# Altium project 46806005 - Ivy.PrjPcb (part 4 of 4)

## Sheet 510_USB_Type_A_Conn.SchDoc: Ivy - Verdin Industrial Board Rev 1.1
size Letter; Organization: Toradex Solutions Inc.; Address1: 6415 Northwest Drive; Address2: Mississauga, ON, L4V 1X1; Address3: Canada
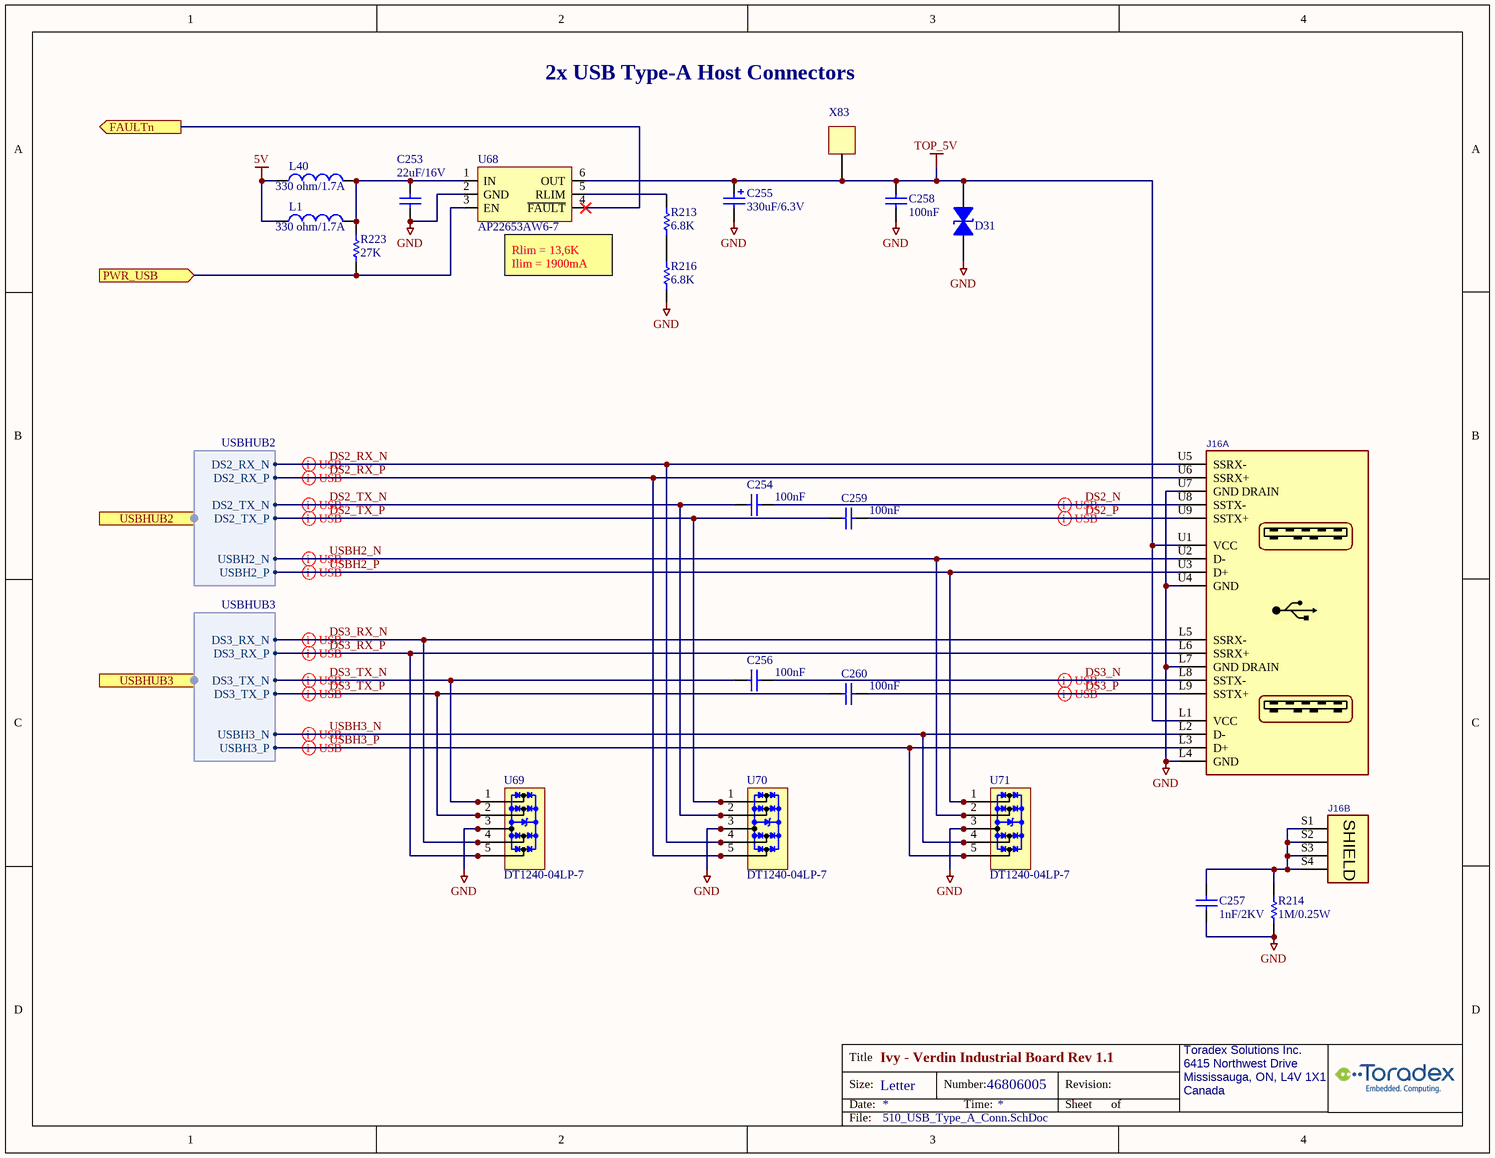
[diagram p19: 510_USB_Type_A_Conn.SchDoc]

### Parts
C253  value 22uF/16V  [C/0805]
C254  100nF  [C0402_CAPC1005L]
C255  330uF/6.3V  [CAN-SMD-D630]
C256  100nF  [C0402_CAPC1005L]
C257  value 1nF/2KV  [C/1206]  (hidden comment: 0567-Cap-1206-1nF/2KV)
C258  100nF  [C0402_CAPC1005L]
C259  100nF  [C0402_CAPC1005L]
C260  100nF  [C0402_CAPC1005L]
D31  D5V0L1B2S9-7  [SOD923_DIO]  (value not drawn)
J16  GSB4112312HR  [T_AMPHENOL_ GSB311231HR]  (value not drawn)  (parts A,B of 2)
L1  value 330 ohm/1.7A  [INDC1608x095]  (hidden comment: 0405-Fer-0603-330ohm/1.7A)
L40  value 330 ohm/1.7A  [INDC1608x095]  (hidden comment: 0405-Fer-0603-330ohm/1.7A)
R213  value 6.8K  [R/0603]  (hidden comment: 0687-Res-0603-6.8K)
R214  value 1M/0.25W  [R/1206]  (hidden comment: 1860-Res-1206-1M-5%-0.25W)
R216  value 6.8K  [R/0603]  (hidden comment: 0687-Res-0603-6.8K)
R223  value 27K  [R0402_RESC1005L]  (hidden comment: 1538-Res-0402-27k)
U68  AP22653AW6-7  [sot23-6]
U69  DT1240-04LP-7  [10-UFDFN]
U70  DT1240-04LP-7  [10-UFDFN]
U71  DT1240-04LP-7  [10-UFDFN]
X83  000-TestPoint  [TestPoint_1]  (value not drawn)

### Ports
FAULTn (out), PWR_USB (in), USBHUB2 (harness USBHUB2), USBHUB3 (harness USBHUB3)

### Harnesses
USBHUB2: USBH2_N, USBH2_P, DS2_TX_N, DS2_TX_P, DS2_RX_N, DS2_RX_P
USBHUB3: USBH3_N, USBH3_P, DS3_TX_N, DS3_TX_P, DS3_RX_N, DS3_RX_P

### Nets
5V: L1.1 L40.1
GND: C253.1 C255.2 C257.1 C258.1 D31.1 J16.L4(GND) J16.L7(GND_DRAIN) J16.U4(GND) J16.U7(GND_DRAIN) R214.2 R216.1 U68.2(GND) U69.3(GND) U69.8(GND) U70.3(GND) U70.8(GND) U71.3(GND) U71.8(GND)
TOP_5V: C255.1 C258.2 D31.2 J16.L1(VCC) J16.U1(VCC) U68.6(OUT) X83.1
DS2_N: C254.1 J16.U8(SSTX-)
DS2_P: C259.1 J16.U9(SSTX+)
DS2_RX_N: J16.U5(SSRX-) U70.4(IO3) U70.7(NC) ; port USBHUB2.DS2_RX_N
DS2_RX_P: J16.U6(SSRX+) U70.5(IO4) U70.6(NC) ; port USBHUB2.DS2_RX_P
DS2_TX_N: C254.2 U70.2(IO2) U70.9(NC) ; port USBHUB2.DS2_TX_N
DS2_TX_P: C259.2 U70.1(IO1) U70.10(NC) ; port USBHUB2.DS2_TX_P
DS3_N: C256.1 J16.L8(SSTX-)
DS3_P: C260.1 J16.L9(SSTX+)
DS3_RX_N: J16.L5(SSRX-) U69.4(IO3) U69.7(NC) ; port USBHUB3.DS3_RX_N
DS3_RX_P: J16.L6(SSRX+) U69.5(IO4) U69.6(NC) ; port USBHUB3.DS3_RX_P
DS3_TX_N: C256.2 U69.1(IO1) U69.10(NC) ; port USBHUB3.DS3_TX_N
DS3_TX_P: C260.2 U69.2(IO2) U69.9(NC) ; port USBHUB3.DS3_TX_P
FAULTn: U68.4(~{FAULT}) ; port FAULTn
PWR_USB: R223.1 U68.3(EN) ; port PWR_USB
USBH2_N: J16.U2(D-) U71.2(IO2) U71.9(NC) ; port USBHUB2.USBH2_N
USBH2_P: J16.U3(D+) U71.1(IO1) U71.10(NC) ; port USBHUB2.USBH2_P
USBH3_N: J16.L2(D-) U71.4(IO3) U71.7(NC) ; port USBHUB3.USBH3_N
USBH3_P: J16.L3(D+) U71.5(IO4) U71.6(NC) ; port USBHUB3.USBH3_P
NetC253_2: C253.2 L1.2 L40.2 R223.2 U68.1(IN)
NetC257_2: C257.2 J16.S1(SHIELD) J16.S2(SHIELD) J16.S3(SHIELD) J16.S4(SHIELD) R214.1
NetR213_1: R213.1 R216.2
NetR213_2: R213.2 U68.5(RLIM)

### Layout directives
differential pair; differential pair class USBH2; differential pair class USB: DS2_N, DS2_P, DS2_RX_N, DS2_RX_P, DS2_TX_N, DS2_TX_P, USBH2_N, USBH2_P
differential pair; differential pair class USBH3; differential pair class USB: DS3_N, DS3_P, DS3_RX_N, DS3_RX_P, DS3_TX_N, DS3_TX_P, USBH3_N, USBH3_P

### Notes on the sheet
- 2x USB Type-A Host Connectors
- (near U68) Rlim = 13,6K
  Ilim = 1900mA

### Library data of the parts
C253 = 1314-Cap-0805-22uF/16V: (-55 to 85 DegC) CAP CER 22uF 16V X5R 0805; MfrNo: CL21A226MOQNNNE; Mfr: Samsung; PN: 1314; Alt: CL21A226MOCLRNC,CL21A226KOQNNNG,GRM21BR61C226ME44L,EMK212BBJ226MG-T
C254 C256 C258-C260 = 1566-Cap-0402-100nF/50V: (-55 to 125 DegC AEC) Cap Ceramic 0.1uF 50V X7R 10% 0402; MfrNo: GRT155R71H104KE01D; Mfr: Murata; Alt: CL05B104KB54PNC,GCM155R71H104ME02D,GCM155R71H104KE02D,GCM155R71H104KE02J; PN: 1566
C255 = 2241-Cap-6.6x6.6-330uF/6.3V: (-55 to 105 DegC) CAP ALUM POLY 33UF 6.3V 20% SMD 10mohm 6.6x6.6x6.1mm Ir:3.9A (100kHz); MfrNo: APXF6R3ARA331MF61G; Mfr: United Chemi-Con; PN: 2241
C257 = 0567-Cap-1206-1nF/2KV: CAP CER 1000PF 2KV X7R 1206; Mfr: Johanson Dielectrics Inc.; MfrNo: 202R18W102KV4E; PN: 567; Alt: 478-2956-1-ND; Alt2: 399-4819-1-ND
D31 = 1655-D5V0L1B2S9-7: (-65 to 155 DegC) TVS DIODE Vwm:5V Vcl:14V@6A SOD-923; Mfr: Diodes; PN: 1655
J16 = 1820-Conn-USB3-2x-RA: (-40 to 85 DegC) Conn USB 3.1 Type A R/A TH; Mfr: Amphenol Commercial; PN: 1820
L1 L40 = 0405-Fer-0603-330ohm/1.7A: (-55 to 125 DegC) FERRITE BEAD 330 OHM 0603 1.7A 80mohm, typ 48mohm; Mfr: TDK Corporation; MfrNo: MPZ1608S331ATA00; PN: 405; TR: 445-5221-2-ND; DR: 445-5221-6-ND; DR2: 810-MPZ1608S331ATA00
R213 R216 = 0687-Res-0603-6.8K: RES SMD 6.8K OHM 1% 1/10W 0603; Mfr: Yageo; MfrNo: RC0603FR-076K8L; PN: 687; TR: 311-6.80KHRTR-ND
R214 = 1860-Res-1206-1M-5%-0.25W: (-55 to 155 DegC) RES SMD 1M OHM 5% 0.25W 10ppm 1206; Mfr: TE Connectivity; MfrNo: CRGCQ1206J1M0; PN: 1860; Alt: RMCF1206JT1M00, RMCF1206JG1M00, CR1206-JW-105ELF
R223 = 1538-Res-0402-27k: (-55 to 155 DegC AEC) RES 27K OHM 1% 1/16W 100ppm 0402; Mfr: Stackpole Electronics; MfrNo: RMCF0402FT27K0; PN: 1538; Alt: AC0402FR-0727KL,CRGCQ0402F27K
U68 = 1475-AP22653: (-40 to 85 DegC) IC PWR SWITCH 3-5.5V EN-Active-High ENth:1.5V With-Discharge 65mohm typ ADJ 0.1-2.1A 6SSOP; Mfr: Diodes; PN: 1475; Note: Similar: BD2222G, BD2242G, TPS25221, TPS2553, RT9728A, RT9728B, RT9728C, AP2553, MIC2009YM6, MIC2019YM6, MIC2009A-1YM6,MIC2019A-1YM6
U69-U71 = 1657-DT1240-04LP-7: (-55 to 85 DegC) IC TVS DIODE 4ch Vrm:5.5V Vcl:11V@5.5A 10-UFDFN 0.5mm; Mfr: Diodes; PN: 1657
X83 = 000-TestPoint: Note: this is PCB footprint only, no parts to buy or assemble

## Sheet 815_IO_Connectors.SchDoc: Ivy - Verdin Industrial Board Rev 1.1
size Letter; Organization: Toradex Solutions Inc.; Address1: 6415 Northwest Drive; Address2: Mississauga, ON, L4V 1X1; Address3: Canada
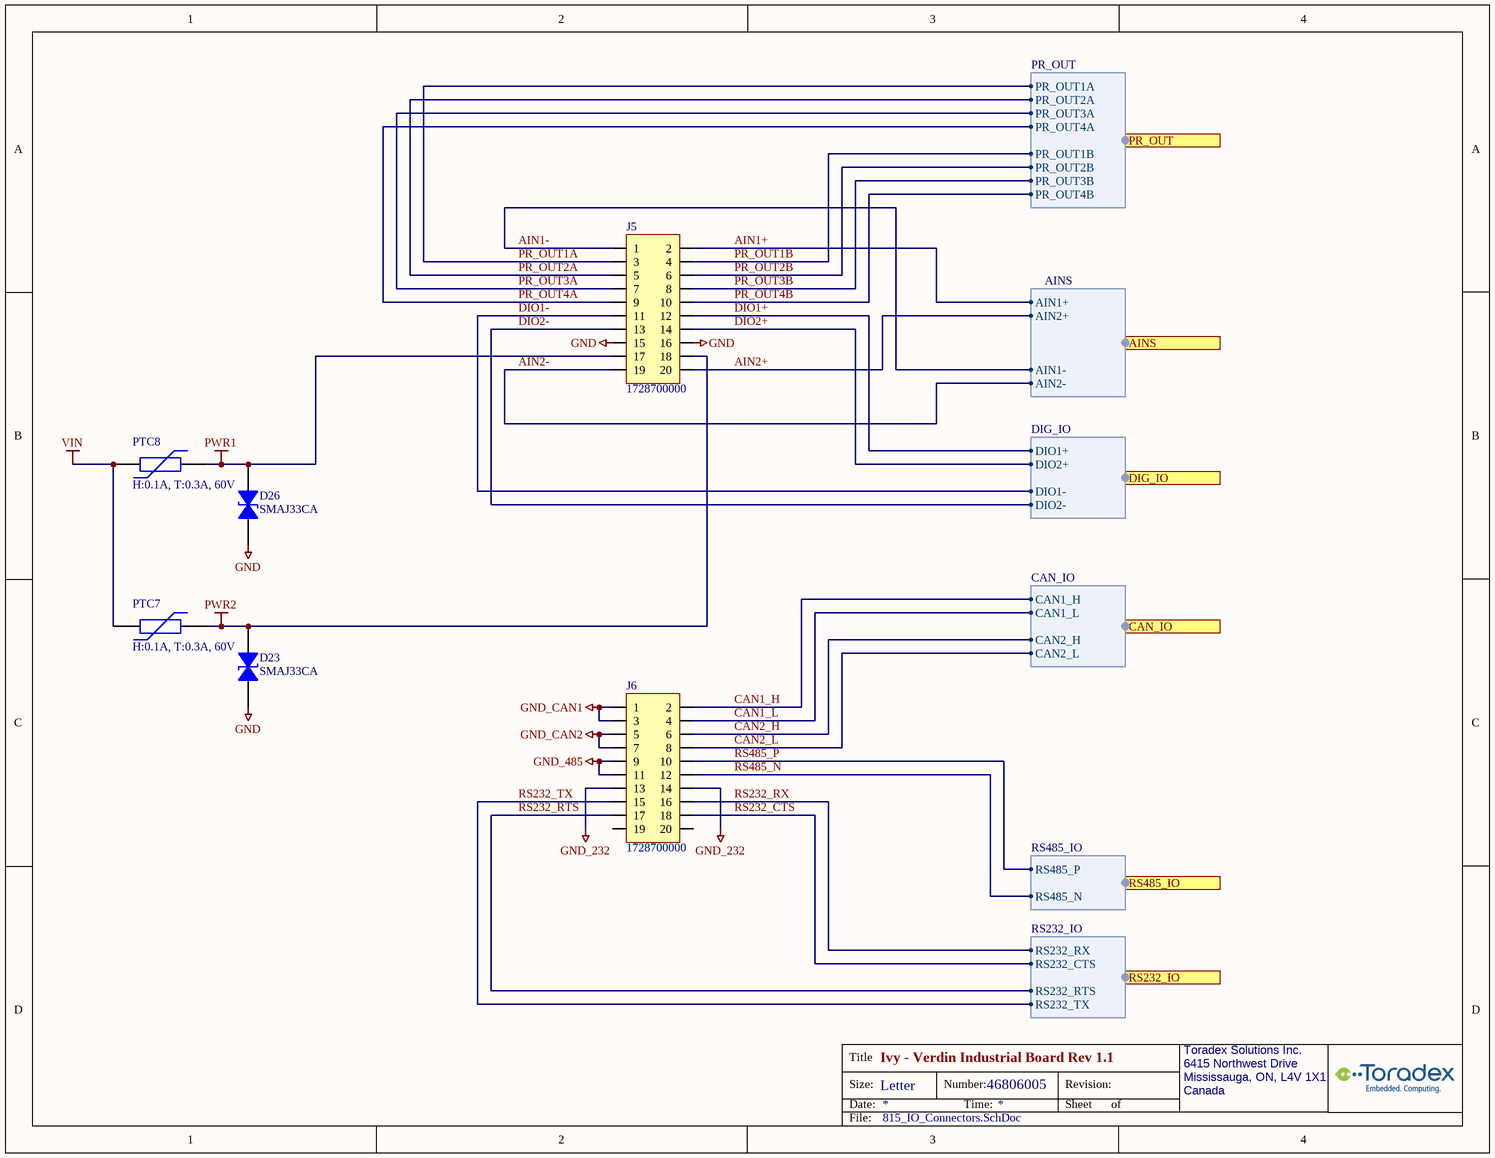
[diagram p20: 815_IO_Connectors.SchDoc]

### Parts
D23  SMAJ33CA  [SMAJ_TRANSIL]
D26  SMAJ33CA  [SMAJ_TRANSIL]
J5  1728700000  [WEIDMULLER_1728700000]
J6  1728700000  [WEIDMULLER_1728700000]
PTC7  H:0.1A, T:0.3A, 60V  [PTC_1812]
PTC8  H:0.1A, T:0.3A, 60V  [PTC_1812]

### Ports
AINS (harness AINS), CAN_IO (harness CAN_IO), DIG_IO (harness DIG_IO), PR_OUT (harness PR_OUT), RS232_IO (harness RS232_IO), RS485_IO (harness RS485_IO)

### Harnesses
PR_OUT: PR_OUT1A, PR_OUT1B, PR_OUT2A, PR_OUT2B, PR_OUT3A, PR_OUT3B, PR_OUT4A, PR_OUT4B
DIG_IO: DIO1+, DIO1-, DIO2+, DIO2-
AINS: AIN1+, AIN1-, AIN2+, AIN2-
CAN_IO: CAN2_H, CAN2_L, CAN1_H, CAN1_L
RS232_IO: RS232_RX, RS232_CTS, RS232_TX, RS232_RTS
RS485_IO: RS485_N, RS485_P

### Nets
GND: D23.2 D26.2 J5.15 J5.16
GND_232: J6.13 J6.14
GND_485: J6.9 J6.11
GND_CAN1: J6.1 J6.3
GND_CAN2: J6.5 J6.7
PWR1: D26.1 J5.17 PTC8.2
PWR2: D23.1 J5.18 PTC7.2
VIN: PTC7.1 PTC8.1
AIN1+: J5.2 ; port AINS.AIN1+
AIN1-: J5.1 ; port AINS.AIN1-
AIN2+: J5.20 ; port AINS.AIN2+
AIN2-: J5.19 ; port AINS.AIN2-
CAN1_H: J6.2 ; port CAN_IO.CAN1_H
CAN1_L: J6.4 ; port CAN_IO.CAN1_L
CAN2_H: J6.6 ; port CAN_IO.CAN2_H
CAN2_L: J6.8 ; port CAN_IO.CAN2_L
DIO1+: J5.12 ; port DIG_IO.DIO1+
DIO1-: J5.11 ; port DIG_IO.DIO1-
DIO2+: J5.14 ; port DIG_IO.DIO2+
DIO2-: J5.13 ; port DIG_IO.DIO2-
PR_OUT1A: J5.3 ; port PR_OUT.PR_OUT1A
PR_OUT1B: J5.4 ; port PR_OUT.PR_OUT1B
PR_OUT2A: J5.5 ; port PR_OUT.PR_OUT2A
PR_OUT2B: J5.6 ; port PR_OUT.PR_OUT2B
PR_OUT3A: J5.7 ; port PR_OUT.PR_OUT3A
PR_OUT3B: J5.8 ; port PR_OUT.PR_OUT3B
PR_OUT4A: J5.9 ; port PR_OUT.PR_OUT4A
PR_OUT4B: J5.10 ; port PR_OUT.PR_OUT4B
RS232_CTS: J6.18 ; port RS232_IO.RS232_CTS
RS232_RTS: J6.17 ; port RS232_IO.RS232_RTS
RS232_RX: J6.16 ; port RS232_IO.RS232_RX
RS232_TX: J6.15 ; port RS232_IO.RS232_TX
RS485_N: J6.12 ; port RS485_IO.RS485_N
RS485_P: J6.10 ; port RS485_IO.RS485_P

Not connected (* = marked no-connect by the designer): J6 19 20

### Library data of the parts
D23 D26 = 0581-SMAJ33CA: (-55 to 150 DegC) TVS DIODE 33VWM Vbrm:36.7V Vcl:53.3V 400W SMA; MfrNo: SMAJ33CA-E3/5A; Mfr: Vishay Semiconductor Diodes Division; PN: 581; Desc: (-55 to 150 DegC) TVS DIODE 33VWM Vbrm:36.7V Vstd:53.3VC SMA; Alt: SMAJ33CA-E3/61GICT-ND; Alt2: SMAJ33CABCT-ND; DR: SMAJ33CA-E3/5AGIDKR-ND; DR2: 625-SMAJ33CA-E3/5A
J5 J6 = 2319-Conn-Hdr-2x10pin-RA-Flanges: (-50 to 100 DegC) TERM BLOCK HDR 20POS 90DEG 3.5MM; Mfr: Weidmuller; PN: 2319
PTC7 PTC8 = 1423-PTC-0.1A-60V-1812: (-40 to 85 DegC) PTC Ih:0.1A, It:0.3A, 60V, 1812, 1.6-15ohm; MfrNo: 0ZCG0010FF2C; Mfr: Bel; PN: 1423; Alt: MPTS1812L010R,MPTS1812L010,1812L010/60DR,PTSA181260V010,MF-MSMF010-2,PFMF.010.2,MINISMDC010F-2,MINIASMDC010F-2

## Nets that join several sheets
1V8: 100_Power (R56.2), 400_USB1_OTG (R58.2 R61.2), 220_Verdin_Full (10 pins), 800_Peripherals (14 pins), 240_Translators (8 pins), 900_LTE (L29.1 R133.1), 300_CAN_Transceivers (L25.1), 620_Ethernet2 (25 pins), 820_MicroSD (R157.2), 840_ADC (9 pins), 850_DIGIN (L32.2)
2V5: 500_USB_Hub (R22.2), 620_Ethernet2 (11 pins)
3V3: 100_Power (9 pins), 600_Ethernet (J10.11 J10.13), 220_Verdin_Full (R270.1 R271.1), 800_Peripherals (J2.3), 240_Translators (7 pins), 900_LTE (L27.1 L28.1), 500_USB_Hub (12 pins), 700_Relays (8 pins), 150_Status_LEDs (Q13.1 R263.2), 620_Ethernet2 (J7.11 J7.13 L26.1), 820_MicroSD (L31.1), 840_ADC (11 pins), 320_RS-232 (5 pins), 330_RS-485 (C219.1 C220.1 U50.1 U51.1), 810_AUX_Connectors (C251.2 J15.25 L33.1)
5V: 100_Power (16 pins), 400_USB1_OTG (L15.1 L16.1 R59.2), 220_Verdin_Full (C3.1), 800_Peripherals (J2.4), 900_LTE (R138.2), 300_CAN_Transceivers (L24.1), 500_USB_Hub (5 pins), 150_Status_LEDs (D5.1 D7.1 D8.1 D9.1), 620_Ethernet2 (R125.2 R126.2), 840_ADC (12 pins), 320_RS-232 (5 pins), 330_RS-485 (6 pins), 810_AUX_Connectors (L34.1), 510_USB_Type_A_Conn (L1.1 L40.1)
GND: 100_Power (56 pins), 600_Ethernet (7 pins), 400_USB1_OTG (17 pins), 220_Verdin_Full (56 pins), 800_Peripherals (26 pins), 240_Translators (6 pins), 900_LTE (35 pins), 300_CAN_Transceivers (20 pins), 500_USB_Hub (62 pins), 700_Relays (8 pins), 150_Status_LEDs (19 pins), 620_Ethernet2 (57 pins), 820_MicroSD (13 pins), 840_ADC (35 pins), 320_RS-232 (12 pins), 330_RS-485 (13 pins), 850_DIGIN (R197.1 R198.1), 810_AUX_Connectors (36 pins), 510_USB_Type_A_Conn (18 pins), 815_IO_Connectors (D23.2 D26.2 J5.15 J5.16)
GND_232: 320_RS-232 (20 pins), 815_IO_Connectors (J6.13 J6.14)
GND_485: 330_RS-485 (19 pins), 815_IO_Connectors (J6.9 J6.11)
GND_CAN1: 300_CAN_Transceivers (18 pins), 815_IO_Connectors (J6.1 J6.3)
GND_CAN2: 300_CAN_Transceivers (18 pins), 815_IO_Connectors (J6.5 J6.7)
SHLD: 000_Main (H1.0 H2.0 H3.0 H4.0), 100_Power (C102.2 R55.1)
VBAT: 220_Verdin_Full (M1.249), 800_Peripherals (X3.1 XS1.2)
VIN: 100_Power (5 pins), 815_IO_Connectors (PTC7.1 PTC8.1)
AIN1+: 840_ADC (D24.1 RA6.2 U37.4), 815_IO_Connectors (J5.2)
AIN1-: 840_ADC (D24.2 PTC5.1), 815_IO_Connectors (J5.1)
AIN2+: 840_ADC (D25.1 RA7.2 U38.4), 815_IO_Connectors (J5.20)
AIN2-: 840_ADC (D25.2 PTC6.1), 815_IO_Connectors (J5.19)
CAN1_H: 300_CAN_Transceivers (J19.2 U22.7 U24.2), 815_IO_Connectors (J6.2)
CAN1_L: 300_CAN_Transceivers (J18.2 U22.6 U24.1), 815_IO_Connectors (J6.4)
CAN1RX_1V8: 220_Verdin_Full (M1.22), 300_CAN_Transceivers (R227.2 R235.1 U20.3)
CAN1TX_1V8: 220_Verdin_Full (M1.20), 300_CAN_Transceivers (R225.2 R234.1 U20.2)
CAN2_H: 300_CAN_Transceivers (J21.2 U23.7 U25.1), 815_IO_Connectors (J6.6)
CAN2_L: 300_CAN_Transceivers (J20.2 U23.6 U25.2), 815_IO_Connectors (J6.8)
CAN2RX_1V8: 220_Verdin_Full (M1.26), 300_CAN_Transceivers (R228.2 R239.1 U21.3)
CAN2TX_1V8: 220_Verdin_Full (M1.24), 300_CAN_Transceivers (R226.2 R238.1 U21.2)
CTRL_RECOVERY_MICO#: 220_Verdin_Full (M1.246), 800_Peripherals (R218.1)
CTRL_RESET_MICO#: 220_Verdin_Full (M1.260), 800_Peripherals (R219.1)
CTRL_RESET_MOCI#: 220_Verdin_Full (M1.258), 800_Peripherals (R8.1), 620_Ethernet2 (R121.1 U26.43)
CTRL_WAKE1_MICO#: 220_Verdin_Full (M1.252), 900_LTE (R132.1)
DIGI_1: 220_Verdin_Full (M1.56), 850_DIGIN (R197.2 U62.3)
DIGI_2: 220_Verdin_Full (M1.58), 850_DIGIN (R198.2 U63.3)
DIO1+: 850_DIGIN (D27.2 D29.1), 815_IO_Connectors (J5.12)
DIO1-: 850_DIGIN (D27.1 U60.3 U62.2), 815_IO_Connectors (J5.11)
DIO2+: 850_DIGIN (D28.2 D30.1), 815_IO_Connectors (J5.14)
DIO2-: 850_DIGIN (D28.1 U61.3 U63.2), 815_IO_Connectors (J5.13)
DS2_RX_N: 500_USB_Hub (U8.44), 510_USB_Type_A_Conn (J16.U5 U70.4 U70.7)
DS2_RX_P: 500_USB_Hub (U8.45), 510_USB_Type_A_Conn (J16.U6 U70.5 U70.6)
DS2_TX_N: 500_USB_Hub (U8.42), 510_USB_Type_A_Conn (C254.2 U70.2 U70.9)
DS2_TX_P: 500_USB_Hub (U8.41), 510_USB_Type_A_Conn (C259.2 U70.1 U70.10)
DS3_RX_N: 500_USB_Hub (U8.36), 510_USB_Type_A_Conn (J16.L5 U69.4 U69.7)
DS3_RX_P: 500_USB_Hub (U8.35), 510_USB_Type_A_Conn (J16.L6 U69.5 U69.6)
DS3_TX_N: 500_USB_Hub (U8.39), 510_USB_Type_A_Conn (C256.2 U69.1 U69.10)
DS3_TX_P: 500_USB_Hub (U8.38), 510_USB_Type_A_Conn (C260.2 U69.2 U69.9)
DSI_1_CLK_N: 220_Verdin_Full (M1.35), 810_AUX_Connectors (L38.2)
DSI_1_CLK_P: 220_Verdin_Full (M1.37), 810_AUX_Connectors (L38.1)
DSI_1_D0_N: 220_Verdin_Full (M1.47), 810_AUX_Connectors (L37.2)
DSI_1_D0_P: 220_Verdin_Full (M1.49), 810_AUX_Connectors (L37.1)
DSI_1_D1_N: 220_Verdin_Full (M1.41), 810_AUX_Connectors (L35.2)
DSI_1_D1_P: 220_Verdin_Full (M1.43), 810_AUX_Connectors (L35.1)
DSI_1_D2_N: 220_Verdin_Full (M1.29), 810_AUX_Connectors (L36.2)
DSI_1_D2_P: 220_Verdin_Full (M1.31), 810_AUX_Connectors (L36.1)
DSI_1_D3_N: 220_Verdin_Full (M1.23), 810_AUX_Connectors (L39.2)
DSI_1_D3_P: 220_Verdin_Full (M1.25), 810_AUX_Connectors (L39.1)
DSI_BKL_EN: 220_Verdin_Full (M1.21), 810_AUX_Connectors (J15.17 R199.2)
DSI_INT: 220_Verdin_Full (M1.17), 810_AUX_Connectors (J15.19 R200.1)
DSI_SCL: 220_Verdin_Full (M1.55), 810_AUX_Connectors (J15.20 R207.1)
DSI_SDA: 220_Verdin_Full (M1.53), 810_AUX_Connectors (J15.21 R208.1)
ETH1_ACT: 600_Ethernet (R2.2), 220_Verdin_Full (M1.237)
ETH1_D0_N: 600_Ethernet (J10.8 U1.2 U1.9), 220_Verdin_Full (M1.227)
ETH1_D0_P: 600_Ethernet (J10.9 U1.1 U1.10), 220_Verdin_Full (M1.225)
ETH1_D1_N: 600_Ethernet (J10.6 U1.5 U1.6), 220_Verdin_Full (M1.231)
ETH1_D1_P: 600_Ethernet (J10.7 U1.4 U1.7), 220_Verdin_Full (M1.233)
ETH1_D2_N: 600_Ethernet (J10.4 U2.2 U2.9), 220_Verdin_Full (M1.241)
ETH1_D2_P: 600_Ethernet (J10.5 U2.1 U2.10), 220_Verdin_Full (M1.239)
ETH1_D3_N: 600_Ethernet (J10.2 U2.5 U2.6), 220_Verdin_Full (M1.245)
ETH1_D3_P: 600_Ethernet (J10.3 U2.4 U2.7), 220_Verdin_Full (M1.247)
ETH1_LINK: 600_Ethernet (R1.2), 220_Verdin_Full (M1.235)
FAULTn: 500_USB_Hub (R217.1), 510_USB_Type_A_Conn (U68.4)
GPIO1: 220_Verdin_Full (M1.206), 800_Peripherals (R9.1 U3.20 X6.1)
I2C1_SCL: 220_Verdin_Full (M1.14), 800_Peripherals (5 pins), 900_LTE (R229.2)
I2C1_SDA: 220_Verdin_Full (M1.12), 800_Peripherals (5 pins), 900_LTE (R230.2)
I2C4_SCL: 220_Verdin_Full (M1.95), 800_Peripherals (J2.14), 840_ADC (R183.1 U47.3 X64.1)
I2C4_SDA: 220_Verdin_Full (M1.93), 800_Peripherals (J2.16), 840_ADC (R184.1 U47.4 X65.1)
I2S_2_BCLK: 220_Verdin_Full (M1.42), 810_AUX_Connectors (R209.1)
JTAG1_TCK: 220_Verdin_Full (M1.9), 810_AUX_Connectors (J13.4 U66.1)
JTAG1_TDI: 220_Verdin_Full (M1.1), 810_AUX_Connectors (J13.8 U67.1)
JTAG1_TDO: 220_Verdin_Full (M1.5), 810_AUX_Connectors (J13.6 U66.3)
JTAG1_TMS: 220_Verdin_Full (M1.13), 810_AUX_Connectors (J13.2 U66.6)
JTAG1_TRST#: 220_Verdin_Full (M1.3), 810_AUX_Connectors (J13.10 U67.6)
NetC97_1: 100_Power (C97.1 R48.1 R49.2), 220_Verdin_Full (M1.2)
NetC100_1: 100_Power (C100.1 R51.1 R52.2), 220_Verdin_Full (M1.4)
NetC101_1: 100_Power (C101.1 R53.1 R54.2), 220_Verdin_Full (M1.6)
NetC103_1: 100_Power (C103.1 R56.1 R57.2), 220_Verdin_Full (M1.8)
NetJ2_8: 220_Verdin_Full (M1.208), 800_Peripherals (J2.8)
NetJ2_10: 220_Verdin_Full (M1.210), 800_Peripherals (J2.10)
NetJ8_36: 900_LTE (J8.36), 500_USB_Hub (U8.59)
NetJ8_38: 900_LTE (J8.38), 500_USB_Hub (U8.60)
NetJ13_1: 220_Verdin_Full (M1.7), 810_AUX_Connectors (J13.1 U67.3)
NetM1_30: 220_Verdin_Full (M1.30), 150_Status_LEDs (Q1.2 R67.2)
NetM1_32: 220_Verdin_Full (M1.32), 150_Status_LEDs (Q1.5 R70.2)
NetM1_34: 220_Verdin_Full (M1.34), 150_Status_LEDs (Q2.2 R71.2)
NetM1_36: 220_Verdin_Full (M1.36), 150_Status_LEDs (Q2.5 R74.2)
NetM1_44: 220_Verdin_Full (M1.44), 150_Status_LEDs (Q3.5 R78.2)
NetM1_46: 220_Verdin_Full (M1.46), 150_Status_LEDs (Q4.2 R79.2)
NetM1_48: 220_Verdin_Full (M1.48), 150_Status_LEDs (Q4.5 R81.2)
NetM1_54: 220_Verdin_Full (M1.54), 150_Status_LEDs (Q3.2 R75.2)
NetM1_57: 220_Verdin_Full (M1.57 R85.1), 900_LTE (R231.2)
NetM1_59: 220_Verdin_Full (M1.59 R224.1), 900_LTE (R232.2)
NetM1_189: 220_Verdin_Full (M1.189), 620_Ethernet2 (R221.1 U26.44)
NetM1_191: 220_Verdin_Full (M1.191), 620_Ethernet2 (R220.1 U26.17)
NetM1_193: 220_Verdin_Full (M1.193), 620_Ethernet2 (U26.16)
NetM1_197: 220_Verdin_Full (M1.197), 620_Ethernet2 (U26.32)
NetM1_199: 220_Verdin_Full (M1.199), 620_Ethernet2 (R118.2 R120.1 U26.38)
NetM1_201: 220_Verdin_Full (M1.201), 620_Ethernet2 (R114.2 R115.1 U26.33)
NetM1_203: 220_Verdin_Full (M1.203), 620_Ethernet2 (U26.34)
NetM1_205: 220_Verdin_Full (M1.205), 620_Ethernet2 (R116.2 R117.2 U26.35)
NetM1_207: 220_Verdin_Full (M1.207), 620_Ethernet2 (U26.36)
NetM1_211: 220_Verdin_Full (M1.211), 620_Ethernet2 (U26.37)
NetM1_212: 220_Verdin_Full (M1.212), 800_Peripherals (R11.1 U6.1 X11.1)
NetM1_213: 220_Verdin_Full (M1.213), 620_Ethernet2 (U26.29)
NetM1_215: 220_Verdin_Full (M1.215), 620_Ethernet2 (U26.25)
NetM1_216: 220_Verdin_Full (M1.216), 840_ADC (U48.2)
NetM1_217: 220_Verdin_Full (M1.217), 620_Ethernet2 (U26.26)
NetM1_218: 220_Verdin_Full (M1.218), 840_ADC (U48.3)
NetM1_219: 220_Verdin_Full (M1.219), 620_Ethernet2 (U26.27)
NetM1_220: 220_Verdin_Full (M1.220), 840_ADC (U48.6)
NetM1_221: 220_Verdin_Full (M1.221), 620_Ethernet2 (U26.28)
NetM1_222: 220_Verdin_Full (M1.222), 840_ADC (U48.7)
PCIE_CLK_N: 220_Verdin_Full (M1.226), 900_LTE (J8.11)
PCIE_CLK_P: 220_Verdin_Full (M1.228), 900_LTE (J8.13)
PCIE_RESET#: 220_Verdin_Full (M1.244), 840_ADC (R276.1 U48.4)
PCIE_RESET_3V: 900_LTE (D19.3), 840_ADC (U48.18)
PCIE_RX_N: 220_Verdin_Full (M1.232), 900_LTE (J8.23)
PCIE_RX_P: 220_Verdin_Full (M1.234), 900_LTE (J8.25)
PCIE_TX_N: 220_Verdin_Full (M1.238), 900_LTE (J8.31)
PCIE_TX_P: 220_Verdin_Full (M1.240), 900_LTE (J8.33)
PR_OUT1A: 700_Relays (D14.2 PTC1.2), 815_IO_Connectors (J5.3)
PR_OUT1B: 700_Relays (D14.1 PR1.3), 815_IO_Connectors (J5.4)
PR_OUT2A: 700_Relays (D15.2 PTC2.2), 815_IO_Connectors (J5.5)
PR_OUT2B: 700_Relays (D15.1 PR2.3), 815_IO_Connectors (J5.6)
PR_OUT3A: 700_Relays (D16.2 PTC3.2), 815_IO_Connectors (J5.7)
PR_OUT3B: 700_Relays (D16.1 PR3.3), 815_IO_Connectors (J5.8)
PR_OUT4A: 700_Relays (D17.2 PTC4.2), 815_IO_Connectors (J5.9)
PR_OUT4B: 700_Relays (D17.1 PR4.3), 815_IO_Connectors (J5.10)
PWM_3_DSI: 220_Verdin_Full (M1.19), 810_AUX_Connectors (J15.18 R201.1 R202.2 X79.1)
PWR_EN: 100_Power (R27.2 U10.1 X15.1), 220_Verdin_Full (R5.1 R6.1), 800_Peripherals (J2.5), 810_AUX_Connectors (U64.3)
PWR_USB: 500_USB_Hub (Q11.3), 510_USB_Type_A_Conn (R223.1 U68.3)
REL1: 220_Verdin_Full (M1.60), 700_Relays (Q5.1 R106.2)
REL2: 220_Verdin_Full (M1.62), 700_Relays (Q6.1 R107.2)
REL3: 220_Verdin_Full (M1.64), 700_Relays (Q7.1 R108.2)
REL4: 220_Verdin_Full (M1.66), 700_Relays (Q8.1 R109.2)
RS232_CTS: 320_RS-232 (U56.8 U57.1), 815_IO_Connectors (J6.18)
RS232_RTS: 320_RS-232 (U56.7 U57.2), 815_IO_Connectors (J6.17)
RS232_RX: 320_RS-232 (U56.13 U58.2), 815_IO_Connectors (J6.16)
RS232_TX: 320_RS-232 (U56.14 U58.1), 815_IO_Connectors (J6.15)
RS485_N: 330_RS-485 (R190.1 U52.7 U59.1), 815_IO_Connectors (J6.12)
RS485_P: 330_RS-485 (J14.2 U52.6 U59.2), 815_IO_Connectors (J6.10)
SD1_CD#: 220_Verdin_Full (M1.84), 820_MicroSD (J12.9 R157.1 U36.5 U36.6)
SD1_CLK: 220_Verdin_Full (M1.78), 820_MicroSD (J12.5 U34.4 U34.7)
SD1_CMD: 220_Verdin_Full (M1.74), 820_MicroSD (J12.3 U36.1 U36.10)
SD1_D0: 220_Verdin_Full (M1.80), 820_MicroSD (J12.7 U34.2 U34.9)
SD1_D1: 220_Verdin_Full (M1.82), 820_MicroSD (J12.8 U34.1 U34.10)
SD1_D2: 220_Verdin_Full (M1.70), 820_MicroSD (J12.1 U36.4 U36.7)
SD1_D3: 220_Verdin_Full (M1.72), 820_MicroSD (J12.2 U36.2 U36.9)
SD1_PWR_EN: 220_Verdin_Full (M1.76), 820_MicroSD (R155.2)
SPI_CLK: 220_Verdin_Full (M1.196), 800_Peripherals (J2.7 U3.19 U6.6 X7.1)
SPI_CS: 220_Verdin_Full (M1.202), 800_Peripherals (J2.12 X12.1)
SPI_MISO: 220_Verdin_Full (M1.198), 800_Peripherals (J2.11 U3.24 U6.2 X4.1)
SPI_MOSI: 220_Verdin_Full (M1.200), 800_Peripherals (J2.9 U3.21 U6.5 X5.1)
UART_1_CTS: 220_Verdin_Full (M1.135), 240_Translators (U16.7)
UART_1_CTS_3V: 240_Translators (RA2.6 U16.15), 320_RS-232 (R246.2 U55.3)
UART_1_RTS: 220_Verdin_Full (M1.133), 240_Translators (RA1.7 U16.3)
UART_1_RTS_3V: 240_Translators (U16.19), 320_RS-232 (R245.2 U55.2)
UART_1_RX_3V: 240_Translators (RA2.5 U16.16), 320_RS-232 (R248.2 U54.3)
UART_1_RXD: 220_Verdin_Full (M1.129), 240_Translators (U16.6)
UART_1_TX_3V: 240_Translators (U16.20), 320_RS-232 (R247.2 U54.2)
UART_1_TXD: 220_Verdin_Full (M1.131), 240_Translators (RA1.8 U16.2)
UART_2_RTS: 220_Verdin_Full (M1.141), 240_Translators (RA1.5 U16.5)
UART_2_RTS_3V: 240_Translators (U16.17), 330_RS-485 (R242.2 U51.2)
UART_2_RX_3V: 240_Translators (RA2.7 U16.14), 330_RS-485 (R185.2 R186.2)
UART_2_RXD: 220_Verdin_Full (M1.137), 240_Translators (U16.8)
UART_2_TX_3V: 240_Translators (U16.18), 330_RS-485 (R189.2 U50.2)
UART_2_TXD: 220_Verdin_Full (M1.139), 240_Translators (RA1.6 U16.4)
USB1_EN: 220_Verdin_Full (M1.155), 840_ADC (R84.2 U48.5)
USB1_EN_3V: 400_USB1_OTG (U14.3 X20.1), 840_ADC (U48.17)
USB1_ID: 400_USB1_OTG (R58.1 U13.9 X19.1), 220_Verdin_Full (M1.161)
USB1_N: 400_USB1_OTG (L18.3), 220_Verdin_Full (M1.163)
USB1_OC#: 400_USB1_OTG (R61.1 U14.4 X22.1), 220_Verdin_Full (M1.157)
USB1_P: 400_USB1_OTG (L18.2), 220_Verdin_Full (M1.165)
USB1_VBUS: 400_USB1_OTG (R63.2 R65.2), 220_Verdin_Full (M1.159)
USB2_EN: 220_Verdin_Full (M1.185), 500_USB_Hub (Q11.2)
USB2_N: 220_Verdin_Full (M1.181), 500_USB_Hub (U8.58)
USB2_P: 220_Verdin_Full (M1.183), 500_USB_Hub (U8.57)
USB_2_SSRX_N: 220_Verdin_Full (M1.175), 500_USB_Hub (U8.5)
USB_2_SSRX_P: 220_Verdin_Full (M1.177), 500_USB_Hub (U8.6)
USB_2_SSTX_N: 220_Verdin_Full (M1.169), 500_USB_Hub (U8.8)
USB_2_SSTX_P: 220_Verdin_Full (M1.171), 500_USB_Hub (U8.9)
USBH2_N: 500_USB_Hub (U8.63), 510_USB_Type_A_Conn (J16.U2 U71.2 U71.9)
USBH2_P: 500_USB_Hub (U8.62), 510_USB_Type_A_Conn (J16.U3 U71.1 U71.10)
USBH3_N: 500_USB_Hub (U8.64), 510_USB_Type_A_Conn (J16.L2 U71.4 U71.7)
USBH3_P: 500_USB_Hub (U8.65), 510_USB_Type_A_Conn (J16.L3 U71.5 U71.6)

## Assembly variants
46801005 - Ivy: not fitted C9 C10 C11 C12 C13 C15 C69 C70 C72 C75 C76 C78 C79 C85 C90 C93 C115 C116 C117 C118 C119 C120 C121 C122 C125 C126 C203 C204 C207 C208 C210 C211 C212 C214 C217 C218 C219 C220 C221 C222 C223 C224 C226 C227 C228 C229 C230 C231 C232 C233 D3 J2 J13 L4 L10 L14 R8 R9 R10 R11 R30 R31 R33 R34 R42 R44 R45 R46 R86 R87 R88 R89 R92 R93 R176 R177 R178 R179 R187 R188 R191 R192 U3 U6 U12 U18 U19 U20 U21 U43 U44 U45 U46 U49 U50 U51 U53 U54 U55 U66 U67
46801015 - Ivy Plus: not fitted C68 C73 C77 C81 C82 C84 C87 J2 J13 L9 L13 R28 R29 R32 R35 R39 R40 R90 R91 R185 R189 R233 R234 R235 R236 R237 R238 R239 R240 R241 R242 R243 R244 R245 R246 R247 R248 R249 R250 R251 R252 R253 R254 R255 R256 R257 R258 R259 R260 R261 R262 U11 U66 U67; alternate parts D1 -> 2062-SMAJ70CA-TP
